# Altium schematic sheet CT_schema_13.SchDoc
size 389 x 278 mm
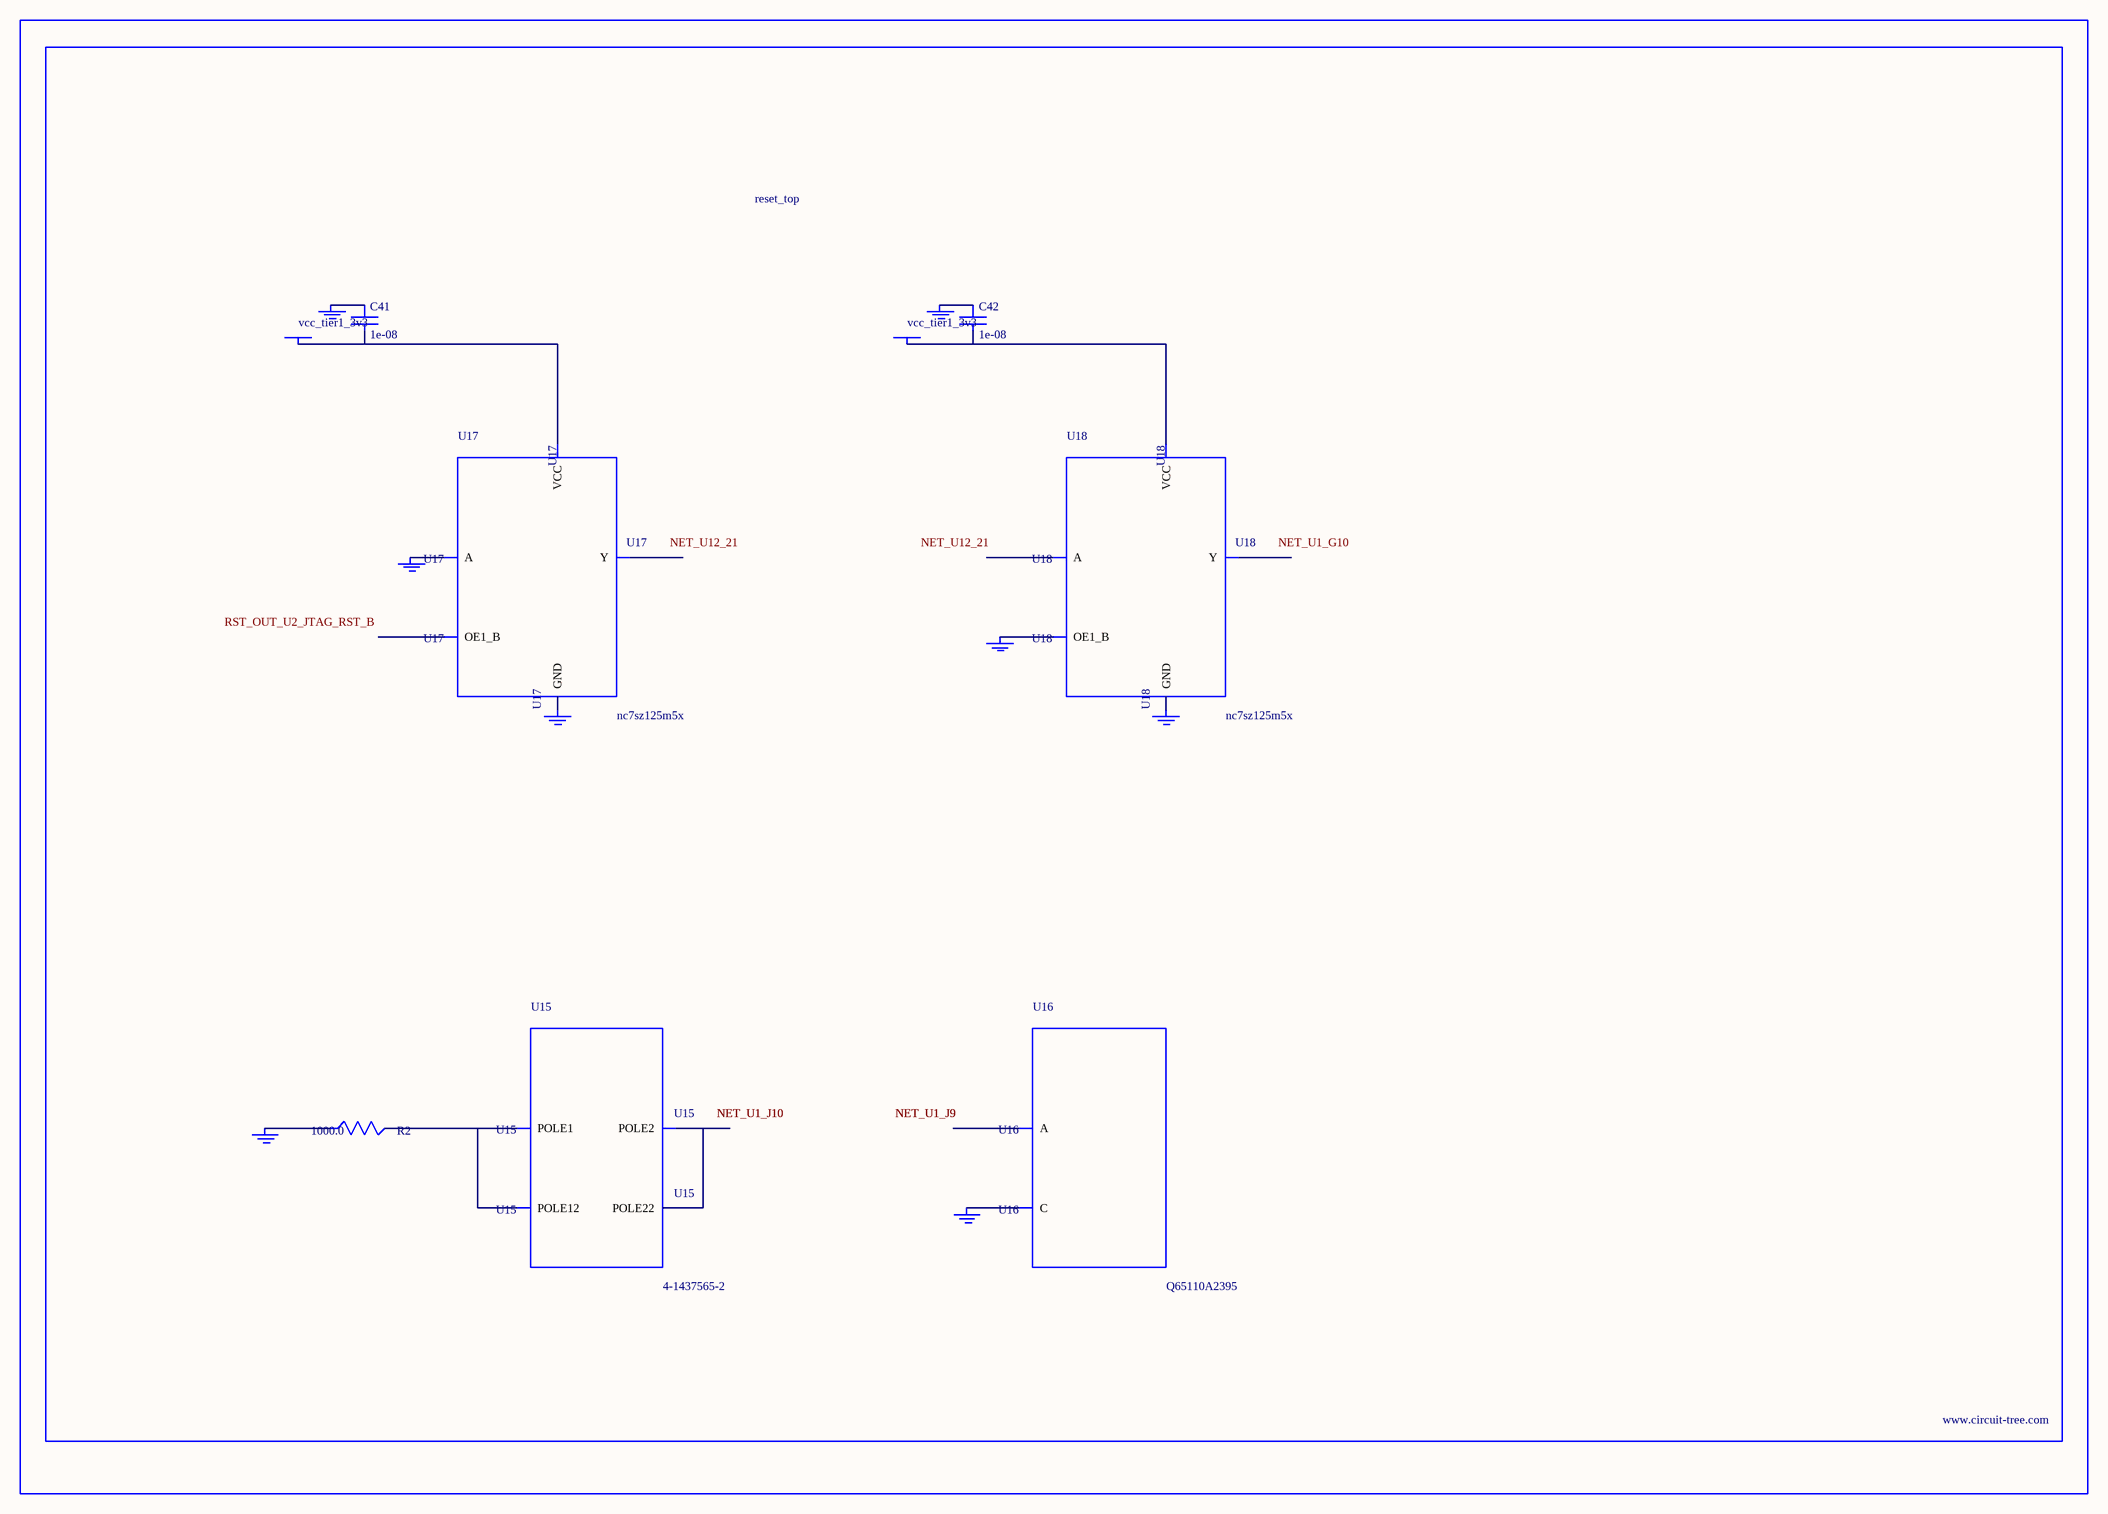
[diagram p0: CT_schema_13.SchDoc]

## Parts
BORDER12  (no value)
C41  1e-08  [C0402]
C42  1e-08  [C0402]
GND_INSTANCE_12_0  (no value)
GND_INSTANCE_12_1  (no value)
GND_INSTANCE_12_2  (no value)
GND_INSTANCE_12_3  (no value)
GND_INSTANCE_12_4  (no value)
GND_INSTANCE_12_5  (no value)
GND_INSTANCE_12_6  (no value)
GND_INSTANCE_12_7  (no value)
POWER_INSTANCE_12_0  vcc_tier1_3v3
POWER_INSTANCE_12_1  vcc_tier1_3v3
R2  1000.0  [R0603]
U15  4-1437565-2  [SW_4-1437565-2]
U16  Q65110A2395  [LGM67K-G1J2-24-Z]
U17  nc7sz125m5x  [NC7SZ125M5X]
U18  nc7sz125m5x  [NC7SZ125M5X]

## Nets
NetC41_1: C41.1 GND_INSTANCE_12_2.0(GND)
NetC41_2: C41.2 POWER_INSTANCE_12_0.0(PWR) U17.5(VCC)
NetC42_1: C42.1 GND_INSTANCE_12_5.0(GND)
NetC42_2: C42.2 POWER_INSTANCE_12_1.0(PWR) U18.5(VCC)
NetGND_INSTANCE_12_0_0: GND_INSTANCE_12_0.0(GND) R2.1
NetGND_INSTANCE_12_1_0: GND_INSTANCE_12_1.0(GND) U16.C
NetGND_INSTANCE_12_3_0: GND_INSTANCE_12_3.0(GND) U17.2(A)
NetGND_INSTANCE_12_4_0: GND_INSTANCE_12_4.0(GND) U17.3(GND)
NetGND_INSTANCE_12_6_0: GND_INSTANCE_12_6.0(GND) U18.1(OE1_B)
NetGND_INSTANCE_12_7_0: GND_INSTANCE_12_7.0(GND) U18.3(GND)
NetR2_2: R2.2 U15.1(POLE1) U15.2(POLE12)
NetU15_3: U15.3(POLE2) U15.4(POLE22)

Not connected (* = marked no-connect by the designer): U16 A; U17 1(OE1_B) 4(Y); U18 2(A) 4(Y)

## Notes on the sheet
- Labels drawn without touching a wire or pin: NET_U1_G10, NET_U12_21, RST_OUT_U2_JTAG_RST_B

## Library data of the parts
BORDER12 = BORDER_PAGE12
C41 C42 = C0402C103K3RAC
GND_INSTANCE_12_0-GND_INSTANCE_12_7 = GND
POWER_INSTANCE_12_0 POWER_INSTANCE_12_1 = PWR
R2 = RC0603JR-071KL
